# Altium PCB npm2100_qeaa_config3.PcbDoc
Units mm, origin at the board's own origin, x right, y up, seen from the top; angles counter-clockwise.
Board outline 9.5 x 8 mm, 2 copper layers (Top Layer, Bottom Layer), stack 1.371 mm thick; 7 components, 10 nets, 29 pads, 21 vias.
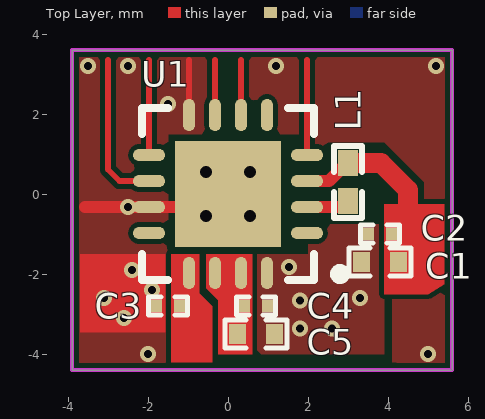
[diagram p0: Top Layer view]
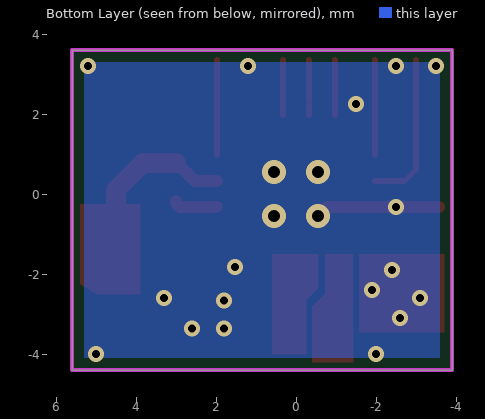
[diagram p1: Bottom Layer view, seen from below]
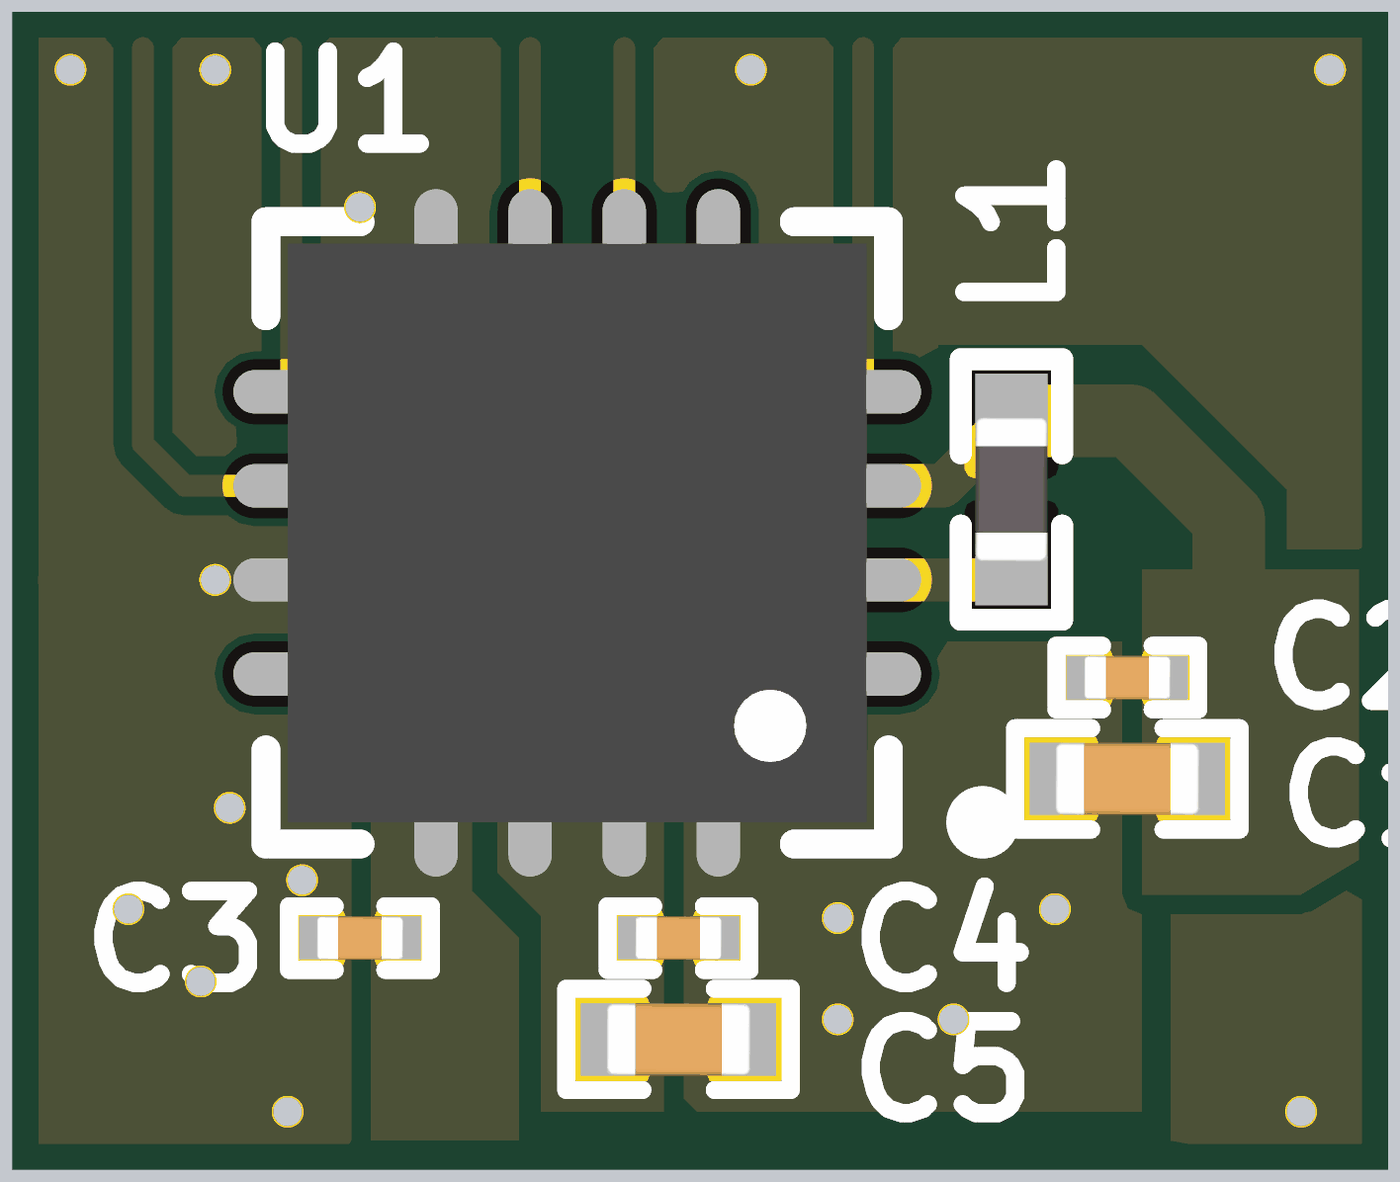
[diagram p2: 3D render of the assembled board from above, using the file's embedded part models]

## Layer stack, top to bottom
Top Solder: solder mask 0.0102, Solder Resist, Dk 3.5
Top Layer: signal copper 0.0356
Dielectric2: core 1.3, FR-4, Dk 4.8
Bottom Layer: signal copper 0.0356
Bottom Solder: solder mask 0.0102, Solder Resist, Dk 3.5

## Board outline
-3.9,-4.4 5.6,-4.4 5.6,3.6 -3.9,3.6

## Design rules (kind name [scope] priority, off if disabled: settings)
BoardOutlineClearance [All] p1: gap=0.15 ignorepadtopadclearanceinfootprint=FALSE
Clearance Polygon_Clearance [(InNamedPolygon('Top_Layer-GND')) or (InNamedPolygon('Bottom_Layer-GND')) or (InNamedPolygon('Mid_Layer_1-GND')) or (InNamedPolygon('Mid_Layer_2-GND'))] p1: gap=0.254 ignorepadtopadclearanceinfootprint=FALSE except(0: Arc-Hole Track-Hole SMDPad-Hole THPad-Hole Via-Hole Fill-Hole Poly-Hole Region-Hole Text-Hole)
Clearance [All] p2: gap=0.125 ignorepadtopadclearanceinfootprint=FALSE
ComponentClearance [All] p1 off: gap=0.254 collisioncheckmode=3 verticalgap=0.254 showdistances=FALSE
DiffPairsRouting [All] p1: maxlimit=0.15 minlimit=0.15 mostfreqgap=0.15 toplayer_minwidth=0.15 toplayer_maxwidth=0.15 toplayer_prefwidth=0.15 bottomlayer_minwidth=0.15 bottomlayer_maxwidth=0.15 bottomlayer_prefwidth=0.15 impedanceprofiledriven=TRUE maxuncoupledlength=12.7
FabricationTestPointUsage TestPointUsage [All] p1: valid=0 allowmultiple=FALSE
FabricationTestpoint Testpoint [All] p1: side=3 testpointundercomponent=TRUE minsize=1.016 maxsize=2.54 preferedsize=1.524 minholesize=0 maxholesize=1.016 preferedholesize=0.813 testpointgrid=0.025 allowsidetop=TRUE allowsidebottom=TRUE usegrid=TRUE gridtolerance=0
Height [All] p1 off: minheight=0 maxheight=25.4 prefheight=12.7
HoleSize [All] p1: absolutevalues=TRUE maxlimit=5 minlimit=0.1 maxpercent=80.000 minpercent=20.000
MinimumAnnularRing [All] p1 off: minimumring=0.1
MinimumSolderMaskSliver [All] p1: minsoldermaskwidth=0.03
PolygonConnect PolygonConnect_GND [InNet('GND')] p1: connectstyle=Direct reliefconductorwidth=0.254 reliefentries=4 polygonreliefangle="90 Angle" airgapwidth=0.254
PolygonConnect [All] p2: connectstyle=Direct reliefconductorwidth=0.254 reliefentries=4 polygonreliefangle="90 Angle" airgapwidth=0.254
RoutingVias [All] p1: holewidth=0.3 width=0.6 viastyle="Through Hole" minholewidth=0.2 minwidth=0.4 maxholewidth=0.5 maxwidth=1
ShortCircuit ShortCircuit_PVSS [InNet('PVSS1') or InNet('PVSS2') or InNet('PVSS3') vs InNet('GND')] p1: allowed=TRUE
ShortCircuit [All] p2: allowed=FALSE
SilkToSilkClearance [All] p1: silktosilkclearance=0.1
SilkToSolderMaskClearance SilkscreenOverComponentPads [IsPad] p1: minsilkscreentomaskgap=0.254 clearancetoexposedcopper=TRUE
SolderMaskExpansion SolderMaskExpansion_Vias [IsVia] p1: expansion=0.102 istentingtop=TRUE
SolderMaskExpansion [All] p2: expansion=0.075 istentingtop=FALSE
UnRoutedNet [All] p1: checkbadconnections=TRUE
Width [All] p1: maxlimit=2 minlimit=0.12 preferedwidth=0.3
19 further rules are at their usual default settings.

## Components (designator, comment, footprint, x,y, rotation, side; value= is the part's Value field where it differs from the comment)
C1 "10µF" CAPC1005X04L_C2 3.8,-1.7 r0 top
C2 "1nF" CAPC0603X03L_C 3.8,-1 r0 top
C3 "2.2µF" CAPC0603X03L_C -1.5,-2.8 r0 top
C4 "1nF" CAPC0603X03L_C 0.7,-2.8 r180 top
C5 "22µF" CAPC1005X04L_C2 0.7,-3.5 r180 top
L1 "2.2µH" INDC1005X04L 3,0.3 r270 top
U1 "nPM2100-QEAA" QFN65P400X400X65_HS-17N 0,0 r180 top

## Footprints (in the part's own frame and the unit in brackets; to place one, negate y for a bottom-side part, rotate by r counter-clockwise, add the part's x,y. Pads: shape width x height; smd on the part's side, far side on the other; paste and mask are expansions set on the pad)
CAPC0603X03L_C [mm] "Chip Capacitor, 2-Leads, Body 0.6x0.3mm, IPC High Density"
  rect 0.27x0.3 smd mask+0.05: 1(-0.285,0) 2(0.285,0)
  silkscreen extent -0.49,-0.22 0.49,0.22, body extent -0.3,-0.15 0.3,0.15, height 0.3
CAPC1005X04L_C2 [mm] "Chip Capacitor, 2-Leads, Body 1.0x0.5mm, IPC High Density"
  rect 0.425x0.5 smd mask+0.05: 1(-0.463,0) 2(0.463,0)
  silkscreen extent -0.77,-0.35 0.77,0.35, body extent -0.5,-0.25 0.5,0.25, height 0.5
INDC1005X04L [mm] "Chip Inductor, 2-Leads, Body 1.0x0.5mm, IPC High Density"
  rect 0.65x0.5 smd: 1(-0.475,0) 2(0.475,0)
  silkscreen extent -0.9,-0.35 0.9,0.35, body extent -0.5,-0.25 0.5,0.25, height 0.5
QFN65P400X400X65_HS-17N [mm] "QFN, 16-Leads, Body 4.00x4.00mm, Pitch 0.65mm, Thermal Pad 2.65x2.65mm, IPC Medium Density"
  oval 0.8x0.3 smd: 1(-1.975,0.975) 2(-1.975,0.325) 3(-1.975,-0.325) 4(-1.975,-0.975) 9(1.975,-0.975) 10(1.975,-0.325) 12(1.975,0.975)
  oval 0.3x0.8 smd: 5(-0.975,-1.975) 6(-0.325,-1.975) 7(0.325,-1.975)
  oval 0.3x0.8 smd mask+0: 8(0.975,-1.975) 13(0.975,1.975) 14(0.325,1.975) 15(-0.325,1.975) 16(-0.975,1.975)
  oval 0.8x0.3 smd mask+0: 11(1.975,0.325)
  rect 2.65x2.65 smd: 17(0,0)
  silkscreen extent -2.93,-2.15 2.15,2.15, body extent -2,-2 2,2, height 0.65

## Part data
C1: library part C0402-10µ-6.3V-X5R-GRM155R60J106ME05D, "Capacitor, X5R, ±20%, 6.3V", Manufacturer=Murata, Manufacturer Part Number=GRM155R60J106ME05D, Part number IPS=N.A., Part number NEMS=100200554, Supplier Part Number 1=490-GRM155R60J106ME05DTR-ND
C2 C4: library part C0201-1n0-50V-X7R, "Capacitor, X7R, ±10pF, 50V", Manufacturer=Murata, Manufacturer Part Number=GRM033R71H102KA12D, Part number IPS=N.A., Part number NEMS=100200404, Supplier Part Number 1=490-10682-1-ND
C3: library part C0201-2.2µ-6V3-X5R-GRM033R60J225ME01, "Capacitor, Ceramic, X5R, ±20%, 6.3V", Manufacturer=Murata, Manufacturer Part Number=GRM033R60J225ME01, Part number IPS=N.A., Part number NEMS=100200660, Supplier Part Number 1=490-GRM033R60J225ME01DTR-ND
C5: library part C0402-22µ-6.3V-X5R-GRM158R60J226ME01D, "Capacitor, X5R, ±20%, 6.3V", Manufacturer=Murata, Manufacturer Part Number=GRM158R60J226ME01D, Part number IPS=N.A., Part number NEMS=100200555, Supplier Part Number 1=490-GRM158R60J226ME01DTR-ND
L1: library part L0402-2µ2-PLEA67BBA2R2M-1PT00, "Inductor, 500mA, ±20%, 620 mOhms", Manufacturer="TDK Corporation", Manufacturer Part Number=PLEA67BBA2R2M-1PT00, Part number IPS=N.A., Part number NEMS=100300496, Supplier Part Number 1=445-PLEA67BBA2R2M-1PT00DKR-ND
U1: "Boost converter companion PMIC for maximum energy extraction of primary (no-rechargeable) batteries", Manufacturer="Nordic Semiconductor", Manufacturer Part Number=nPM2100_QEAA, Part number IPS=N.A., Part number NEMS=102000298

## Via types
v1: diameter 0.4, hole 0.2, Top Layer to Bottom Layer, tented both sides, 17 vias
v2: diameter 0.61, hole 0.305, Top Layer to Bottom Layer, tented both sides, 4 vias

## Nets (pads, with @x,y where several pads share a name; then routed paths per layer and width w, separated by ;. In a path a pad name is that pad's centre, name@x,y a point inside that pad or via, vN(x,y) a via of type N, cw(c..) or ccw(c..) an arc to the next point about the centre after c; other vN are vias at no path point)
GND: C1.1 C2.1 C3.1 C4.1 C5.1 U1.8 U1.11 U1.16 U1.17 | length 4.5
  Top Layer w0.15: U1.8 -0.975,3.35
  Top Layer w0.3: -3.575,-0.325 U1.11 -0.775,-0.325 v2(-0.55,-0.55)
  other v1: -2,-4 5,-4 1.8,-3.362 2.6,-3.362 -2.6,-3.1 1.8,-2.662 -3.1,-2.6 3.3,-2.6 -1.9,-2.4 -2.4,-1.9 1.525,-1.825 -2.5,-0.325 -1.5,2.25 -3.5,3.2 -2.5,3.2 1.2,3.2 5.2,3.2
  other v2: 0.55,-0.55 -0.55,0.55 0.55,0.55
GPIO1: U1.9 | length 2.4
  Top Layer w0.15: U1.9 -1.975,3.35
PG/RESET: U1.10 | length 3.9
  Top Layer w0.15: -3,3.35 -3,0.613 -2.712,0.325 U1.10
SCL: U1.7 | length 1.3
  Top Layer w0.15: U1.7 U1.7@-0.325,2.266 ; U1.7@-0.325,2.341 -0.325,3.35
SDA: U1.6 | length 1.4
  Top Layer w0.15: U1.6 0.325,3.35
SHPHLD: U1.4 | length 2.4
  Top Layer w0.15: U1.4 1.975,3.35
SW: L1.2 U1.2 | length 1.1
  Top Layer w0.3: U1.2 2.9,-0.325 3,-0.225 L1.2
VBAT: C1.2 C2.2 L1.1 U1.3 | length 4.6
  Top Layer w0.3: U1.3 2.525,0.325 L1.1@2.849,0.649
  Top Layer w0.5: L1.1 3.825,0.775 4.5,0.1 4.5,-1 4.5,-1.25 4.5,-1.45 4.5,-1.75
VINT: C4.2 C5.2 U1.14 U1.15
VOUT: C3.2 U1.13
pads on no net: U1.1 U1.5 U1.12

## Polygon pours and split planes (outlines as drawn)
GND on Bottom Layer "Bottom_Layer-GND" (solid, remove dead copper, pour order 7): -4,-4.5 -4,3.75 5.75,3.75 5.75,-4.5
GND on Top Layer "NONET_L-01_P-001" (solid, pour order 8): -4,-4.5 5.75,-4.5 5.75,3.75 -4,3.75

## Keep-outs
Keep-Out Layer:
  the board outline again, w0.1

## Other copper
Top Layer:
  region net VINT: 0.6,-4 0.6,-1.5 -0.55,-1.5 -0.55,-2.35 -0.25,-2.65 -0.25,-4
  pour cut-out: 3.9,-2.5 3.9,-4 -0.3,-4 -0.3,-4.2 4.1,-4.2 4.1,-2.5
  region net VBAT: 5.4,-0.25 3.9,-0.25 3.9,-2.5 5,-2.5 5.4,-2.26
  pour cut-out: -1.5,1.5 -1.5,-1.5 2.005,-1.5 2.005,1.5
  region net VOUT: -0.4,-4.2 -0.4,-2.8 -0.725,-2.475 -0.725,-1.5 -1.425,-1.5 -1.425,-4.2
  region net GND: -3.7,-3.462 -3.7,-1.5 -1.575,-1.5 -1.575,-3.462
  pour cut-out: 2.492,1.3 3.9,1.3 4.9,0.3 4.9,-0.75 2.492,-0.75

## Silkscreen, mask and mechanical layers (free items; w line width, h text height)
Mechanical 1:
  the board outline again, w0.2

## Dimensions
-3.9,-4.4 to 5.6,-4.4 on Mechanical 3
5.6,3.6 to 5.6,-4.4 on Mechanical 3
